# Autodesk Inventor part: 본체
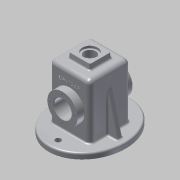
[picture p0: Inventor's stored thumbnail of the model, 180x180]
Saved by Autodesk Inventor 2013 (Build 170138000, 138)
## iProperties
Created: 2017-07
Part Number: 본체
Material: 알루미늄 6061
Document SubType Name: Modeling
Designer: Administrator
Density: 2.71 g/cm^3
Mass: 892.664 g
Surface Area: 988.091 cm^2
Volume: 329.396 cm^3
Author: Administrator
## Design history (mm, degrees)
sketch "스케치1"
  geometry: 1 further point
sketch "스케치2"
  geometry: L1 (37, -55)-(-37, -55); L2 (-37, -55)-(-37, 55); L3 (-37, 55)-(37, 55); L4 (37, 55)-(37, -55); L5 (37, -55)-(-37, 55); L6 (-37, -55)-(37, 55); 1 further point
  constraints: 12 end point, 2 midpoint, 2 parallel, 1 horizontal, 1 perpendicular
  dimensions: "d0" = 110 distance of L1.end L2.end; "d2" = 74 distance of L2.end L3.end
extrude "돌출1" new body sketch "스케치2" stored distance "d3" = 74; taper "d4" = 0 deg
feature "쉘1" dims "d13" = 5
sketch "스케치5"
  geometry: C1 r 27.5 at (0, 0); 1 further point
  constraints: 1 centre point, 1 coincident
  dimensions: "d14" = 55 diameter of C1
extrude "돌출4" join sketch "스케치5" distance "d16" = 13; taper "d17" = 0 deg
sketch "스케치6"
  geometry: C1 r 27.5 at (0, 0); 1 further point
  constraints: 1 centre point, 1 coincident
  dimensions: "d18" = 55 diameter of C1
extrude "돌출5" join sketch "스케치6" distance "d20" = 13; taper "d21" = 0 deg
sketch "스케치7"
  geometry: C1 r 27.5 at (0, 0) reference; C2 r 16 at (0, 0)
  constraints: 1 centre point, 1 coincident
  dimensions: "d22" = 32 diameter of C2
extrude "돌출6" cut sketch "스케치7" stored distance "d24" = 13; taper "d25" = 0 deg
sketch "스케치8"
  geometry: L1 (32, 16)-(50, 16) reference; L2 (37, 27.5)-(50, 27.5) reference; L3 (32, -55)-(32, 50) reference; L4 (32, -16)-(50, -16) reference; L5 (37, -27.5)-(50, -27.5) reference; L6 (-32, 50)-(-32, -55) reference; L7 (-50, 16)-(-32, 16) reference; L8 (-37, 27.5)-(-50, 27.5) reference; L9 (-50, -16)-(-32, -16) reference; L10 (-37, -27.5)-(-50, -27.5) reference; L11 (-50, -16)-(-50, 16) reference; L12 (50, 16)-(50, -16) reference; L13 (-50, 0)-(50, 0); L14 (32, 16)-(25, 16); L15 (25, 16)-(25, 20.5); L16 (25, 20.5)-(32, 27.5); L17 (-32, 16)-(-25, 16); L18 (-25, 16)-(-25, 20.5); L19 (-25, 20.5)-(-32, 27.5); 3 further points
  constraints: 14 end point, 4 perpendicular, 3 midpoint, 2 point on line, 1 horizontal alignment, 1 parallel
  dimensions: "d26" = 7 distance between parallel lines of L3 L15; "d27" = 135 deg angle of L3 L16; "d28" = 55 diameter of L16.end L13; "d29" = 7 distance between parallel lines of L6 L18; "d30" = 55 diameter of L19.end L13
revolve "회전1" sketch "스케치8" stored, may be unused: angle "d31" = 90 deg
sketch "스케치9"
  geometry: L1 (17, -57)-(57, -57); L2 (57, -57)-(57, -17); L3 (57, -17)-(17, -17); L4 (17, -17)-(17, -57); L5 (17, -57)-(57, -17); L6 (57, -57)-(17, -17); 1 further point
  constraints: 12 end point, 2 midpoint, 2 parallel, 1 horizontal, 1 perpendicular
  dimensions: "d32" = 40 distance of L2.end L3.end; "d34" = 40 distance of L3.end L1.start
extrude "돌출7" join sketch "스케치9" distance "d35" = 10; taper "d36" = -5 deg
sketch "스케치10"
  geometry: C1 r 14 at (37, -37); 1 further point
  constraints: 1 centre point, 1 coincident
  dimensions: "d37" = 28 diameter of C1
extrude "돌출8" cut sketch "스케치10" distance "d39" = 4; taper "d40" = 0 deg
sketch "스케치11"
  geometry: C1 r 14 at (0, 0) reference; C2 r 10.5 at (0, 0)
  constraints: 1 centre point, 1 coincident
  dimensions: "d41" = 21 diameter of C2
extrude "돌출9" cut sketch "스케치11" stored distance "d43" = 4; taper "d44" = 0 deg
sketch "스케치12" dims "d45" = 75, "d47" = 65
  geometry: L1 (69, -5)-(69, -69) reference; L2 (74, -74)-(74, 0) reference; L3 (0, 0)-(74, 0) reference; L4 (0, 0)-(0, -74) reference; L5 (74, -74)-(0, -74) reference; 2 further points; 1 other entity
  constraints: 1 coincident, 1 vertical, 2 other
extrude "돌출10" join sketch "스케치12" distance "d48" = 10; taper "d49" = 0 deg
sketch "스케치13"
  geometry: L1 (-37, -95)-(-37, 21); C1 r 5 at (-37, -95); C2 r 5 at (-37, 21); 2 further points; 1 other entity
  constraints: 2 centre point, 2 coincident, 2 end point, 2 vertical alignment, 1 equal radius, 1 midpoint, 1 vertical, 1 other
  dimensions: "d50" = 116 distance of L1.start L1.end; "d52" = 58 distance of L1.start point (-37, -37); "d53" = 10 diameter of C1
extrude "돌출11" cut sketch "스케치13" distance "d54" = 10; taper "d55" = 0 deg
sketch "스케치14"
  geometry: L1 (37, 55)-(37, -45) reference; L2 (65, -45)-(-65, -45) reference; L3 (37, 27.194)-(55, -45); L4 (65, -45)-(-65, -45) reference; L5 (65, -55)-(-65, -55) reference; L6 (32, 50)-(32, -55) reference; L7 (65, -55)-(65, -45); 1 further point
  constraints: 4 end point, 2 point on line, 1 parallel
  dimensions: "d57" = 10 distance of L2.start L3.end; "d59" = 14 deg angle of L7 L3
feature "리브1" sketch "스케치14" dims "d60" = 1, "d61" = 10, "d62" = 0, "d63" = 0, "d64" = 1, "d65" = 1
sketch "스케치15"
  geometry: L1 (-37, -45)-(-37, 55) reference; L2 (65, -45)-(-65, -45) reference; L3 (65, -55)-(-65, -55) reference; L4 (-65, -55)-(-65, -45); L5 (-55, -45)-(-37, 27.194); 1 further point
  constraints: 4 end point, 2 point on line, 1 perpendicular
  dimensions: "d67" = 14 deg angle of L5 L4; "d68" = 10 distance from line of L4 L5.start
feature "리브2" sketch "스케치15" dims "d69" = 1, "d70" = 10, "d71" = 0, "d72" = 0, "d73" = 1, "d74" = 1
sketch "스케치16" dims "d75" = 45
  geometry: C1 r 16 at (0, 0) reference; C2 r 27.5 at (0, 0) reference; C3 r 4.987 at (0, 22.5); 1 further point
  constraints: 2 vertical alignment, 1 centre point, 1 coincident, 2 other
sketch "스케치17" dims "d77" = 45
  geometry: C1 r 16 at (0, 0) reference; C2 r 27.5 at (0, 0) reference; C3 r 3.948 at (0, -22.5); 1 further point
  constraints: 2 vertical alignment, 1 centre point, 1 coincident, 2 other
hole "구멍1" sketch "스케치16" diameter "d79" = 3.242; stored, may be unused: countersink angle "d83" = 90 deg, drill point angle "d85" = 118 deg; dims "d80" = 8, "d81" = 4, "d82" = 2, "d84" = 10
hole "구멍2" sketch "스케치17" diameter "d86" = 3.242; stored, may be unused: countersink angle "d90" = 90 deg, drill point angle "d92" = 118 deg; dims "d87" = 8, "d88" = 4, "d89" = 2, "d91" = 10
fillet "모깎기1" dims "d96" = 8
fillet "모깎기2" dims "d97" = 8
fillet "모깎기3" dims "d98" = 3
fillet "모깎기4" dims "d99" = 3
fillet "모깎기5" dims "d100" = 0.5
chamfer "모따기1" distance "d101" = 1; stored, may be unused: second distance "d102" = 2, angle "d103" = 45 deg
fillet "모깎기6" dims "d104" = 3
fillet "모깎기7" dims "d105" = 3
fillet "모깎기8" dims "d106" = 3
fillet "모깎기9" dims "d107" = 3
fillet "모깎기10" dims "d108" = 3
fillet "모깎기11" dims "d109" = 3
sketch "스케치18"
  geometry: L1 (-20.739, 38.002)-(20.739, 38.002); L2 (20.739, 38.002)-(20.739, 31.998); L3 (20.739, 31.998)-(-20.739, 31.998); L4 (-20.739, 31.998)-(-20.739, 38.002); L5 (-20.739, 35)-(20.739, 35); L6 (0, 38.002)-(0, 31.998); L7 (16.137, 65)-(-16.137, 65) reference; L8 (37, -42)-(37, 47) reference
  constraints: 4 end point, 4 midpoint, 2 other
  dimensions: "d110" = 41.47897 distance of L1.start L1.end; "d112" = 6.00407 distance of L3.end L1.start; "d113" = 30 distance between parallel lines of L7 L5; "d114" = 37 distance between parallel lines of L8 L6
extrude "돌출12" join sketch "스케치18" distance "d115" = 0.5; taper "d116" = 0 deg
fillet "모깎기12" dims "d117" = 0.5
node "솔리드1"
pattern_circular "원형 패턴1" dims angle "d94" = 360 deg
node "투영된 루프1"
